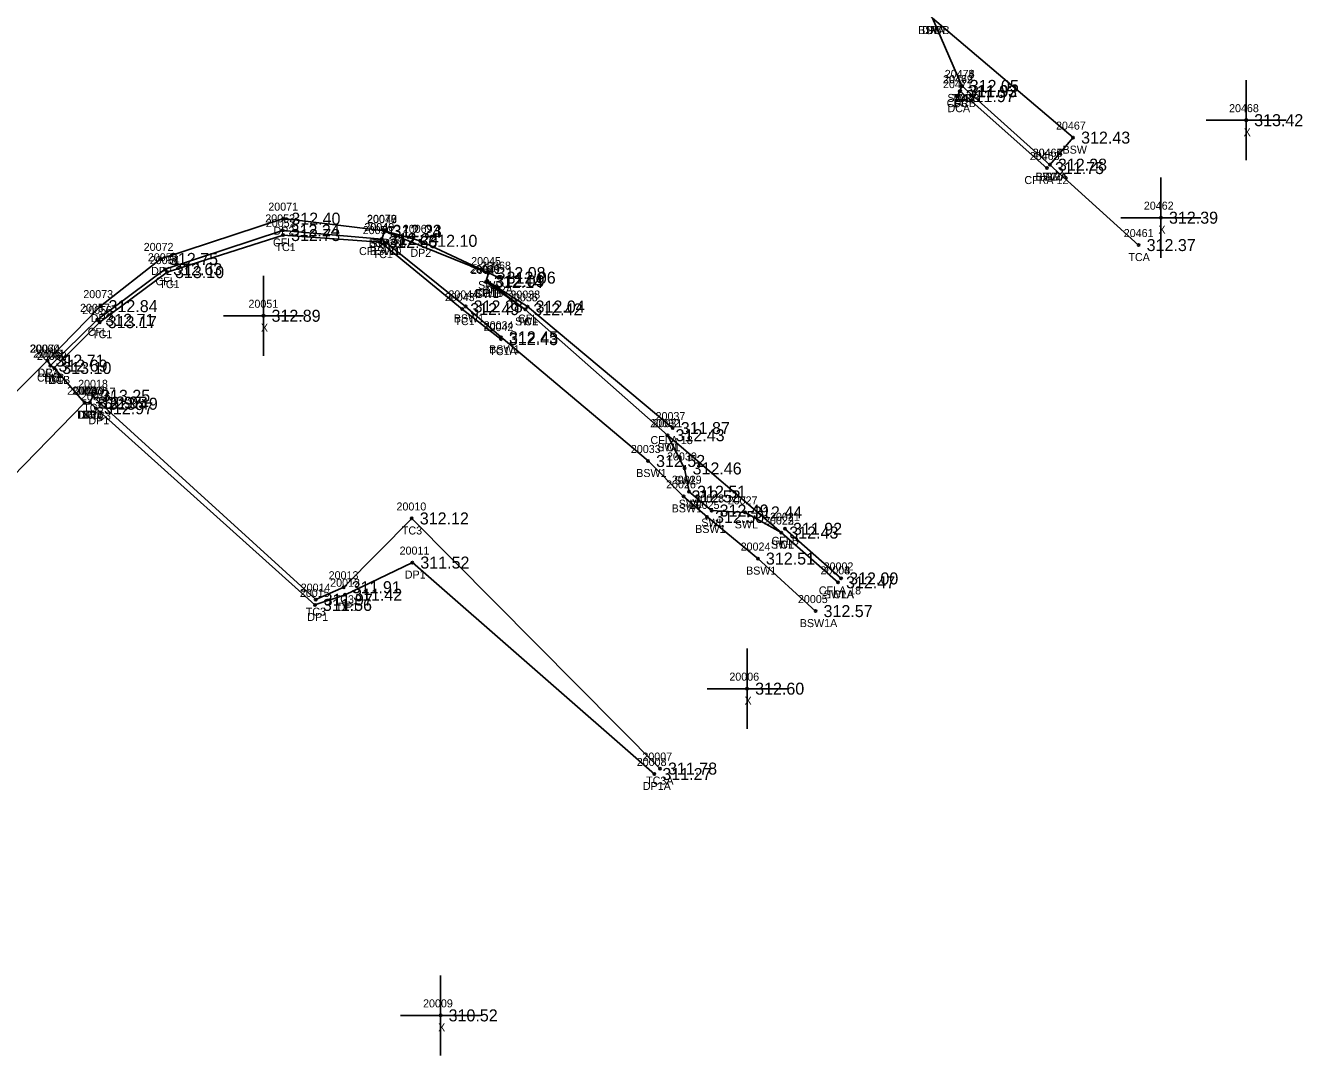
# Model space of a CAD drawing. Extents: x 1970242 to 1971082, y 803104 to 803947.
# Drawn here: x 1970893.2 to 1971052.8, y 803104.4 to 803233.1 of the extents above; entities that cross this region are included whole.
import ezdxf

# ---------------------------------------------------------------- set-up
doc = ezdxf.new("R2010")
doc.units = 0
for name, color, linetype in [('RD_DTM_BkLn2', 7, 'Continuous'), ('RD_EX_Conc', 7, 'Continuous'), ('RD_EX_Conc_txCode', 7, 'Continuous'), ('RD_EX_Driveway', 7, 'Continuous'), ('RD_EX_Driveway_txCode', 7, 'Continuous'), ('RD_EX_Misc', 7, 'Continuous'), ('RD_EX_Misc_txCode', 7, 'Continuous'), ('RD_EX_TX_Conc_ELEV', 7, 'Continuous'), ('RD_EX_TX_Driveway_ELEV', 7, 'Continuous'), ('RD_EX_TX_Misc_ELEV', 7, 'Continuous'), ('RD_SMD_Locator', 7, 'Continuous')]:
    doc.layers.add(name, color=color, linetype=linetype)

msp = doc.modelspace()

# ---------------------------------------------------------------- linework, layer by layer
at = {"layer": 'RD_DTM_BkLn2'}
for points in [[(1971032.36, 803205.64), (1971021.27, 803215.68), (1971010.25, 803225.52)], [(1970952.66, 803193.89), (1970947.82, 803197.64), (1970937.59, 803206.01), (1970925.44, 803206.89), (1970910.93, 803202.26), (1970902.52, 803196.01), (1970896.84, 803190.29)], [(1970994.79, 803163.51), (1970987.7, 803169.73), (1970973.48, 803181.89), (1970955.71, 803197.61), (1970950.97, 803201.14)], [(1970972.54, 803140.25), (1970941.52, 803171.49), (1970933.01, 803162.9), (1970929.51, 803161.35), (1970902.64, 803185.82), (1970901.69, 803186.81), (1970901.29, 803185.97)]]:
    msp.add_lwpolyline(points, dxfattribs=at)
at = {"layer": 'RD_EX_Conc'}
for p, q in [((1971021.27, 803215.68), (1971010.25, 803225.52)), ((1971020.9, 803215.26), (1971010.07, 803224.87)), ((1970995.18, 803164), (1970988.16, 803170.2))]:
    msp.add_line(p, q, dxfattribs=at)
for points in [[(1971009.74, 803224.24), (1971010.01, 803224.85), (1971010.25, 803225.52), (1971006.59, 803233.99), (1970934.65, 803298.46), (1970929.07, 803297.51), (1970928.19, 803297.32), (1970927.5, 803297.02)], [(1971021.27, 803215.68), (1971024.17, 803219.06), (1971006.59, 803233.99)], [(1970937.76, 803206.39), (1970925.37, 803207.47), (1970910.7, 803202.62), (1970902.22, 803196.3), (1970896.36, 803190.58)], [(1970991.98, 803159.92), (1970984.78, 803166.48), (1970978.42, 803171.68), (1970975.48, 803174.25), (1970971.05, 803178.67), (1970952.67, 803194.12), (1970948.25, 803197.98), (1970937.76, 803206.39), (1970938.1, 803207.37)], [(1970994.79, 803163.51), (1970987.7, 803169.73), (1970983.17, 803172.25), (1970978.99, 803172.48), (1970976.18, 803174.83), (1970975.61, 803177.74), (1970973.48, 803181.89), (1970955.71, 803197.61), (1970950.79, 803201.04), (1970951.1, 803202.14), (1970938.1, 803207.37)], [(1970974.14, 803182.78), (1970955.99, 803197.96), (1970950.97, 803201.14)], [(1970895.99, 803191.21), (1970896.36, 803190.58), (1970896.84, 803190.29), (1970900.63, 803185.94), (1970885.6, 803170.52), (1970879.45, 803174.56)]]:
    msp.add_lwpolyline(points, dxfattribs=at)
at = {"layer": 'RD_EX_Driveway'}
for points in [[(1970952.37, 803201.57), (1970942.58, 803206.17), (1970938.12, 803207.42), (1970925.47, 803208.94), (1970910.17, 803203.91), (1970902.62, 803198.01), (1970895.99, 803191.21), (1970879.38, 803174.75)], [(1970971.84, 803139.57), (1970941.59, 803165.98), (1970933.19, 803161.96), (1970929.41, 803160.69), (1970902.05, 803185.25), (1970901.29, 803185.97), (1970900.63, 803185.94), (1970885.6, 803170.52)]]:
    msp.add_lwpolyline(points, dxfattribs=at)
at = {"layer": 'RD_EX_Misc'}
for p, q in [((1971045.8, 803216.24), (1971045.8, 803226.24)), ((1971040.8, 803221.24), (1971050.8, 803221.24)), ((1971035.15, 803204.06), (1971035.15, 803214.06)), ((1971030.15, 803209.06), (1971040.15, 803209.06)), ((1970922.99, 803191.81), (1970922.99, 803201.81)), ((1970917.99, 803196.81), (1970927.99, 803196.81)), ((1970983.43, 803145.23), (1970983.43, 803155.23)), ((1970978.43, 803150.23), (1970988.43, 803150.23)), ((1970945.12, 803104.42), (1970945.12, 803114.42)), ((1970940.12, 803109.42), (1970950.12, 803109.42))]:
    msp.add_line(p, q, dxfattribs=at)
at = {"layer": 'RD_SMD_Locator'}
for centre in [(1971010.25, 803225.52), (1971010.25, 803225.52), (1971010.25, 803225.52), (1971009.74, 803224.24), (1971010.01, 803224.85), (1971010.07, 803224.87), (1971045.8, 803221.24), (1971024.17, 803219.06), (1971021.27, 803215.68), (1971021.27, 803215.68), (1971021.27, 803215.68), (1971020.9, 803215.26), (1970925.47, 803208.94), (1971035.15, 803209.06), (1970925.37, 803207.47), (1970925.44, 803206.89), (1970937.76, 803206.39), (1970937.76, 803206.39), (1970938.1, 803207.37), (1970938.1, 803207.37), (1970938.12, 803207.42), (1970942.58, 803206.17), (1970937.59, 803206.01), (1971032.36, 803205.64), (1970910.17, 803203.91), (1970910.7, 803202.62), (1970910.93, 803202.26), (1970951.1, 803202.14), (1970952.37, 803201.57), (1970950.79, 803201.04), (1970950.97, 803201.14), (1970950.97, 803201.14), (1970902.62, 803198.01), (1970922.99, 803196.81), (1970947.82, 803197.64), (1970948.25, 803197.98), (1970955.71, 803197.61), (1970955.71, 803197.61), (1970955.99, 803197.96), (1970902.22, 803196.3), (1970902.52, 803196.01), (1970952.66, 803193.89), (1970952.67, 803194.12), (1970895.99, 803191.21), (1970895.99, 803191.21), (1970896.36, 803190.58), (1970896.36, 803190.58), (1970896.84, 803190.29), (1970896.84, 803190.29), (1970900.63, 803185.94), (1970900.63, 803185.94), (1970901.29, 803185.97), (1970901.29, 803185.97), (1970901.69, 803186.81), (1970902.64, 803185.82), (1970902.05, 803185.25), (1970974.14, 803182.78), (1970973.48, 803181.89), (1970973.48, 803181.89), (1970971.05, 803178.67), (1970975.61, 803177.74), (1970975.48, 803174.25), (1970976.18, 803174.83), (1970941.52, 803171.49), (1970978.42, 803171.68), (1970978.99, 803172.48), (1970983.17, 803172.25), (1970987.7, 803169.73), (1970987.7, 803169.73), (1970988.16, 803170.2), (1970984.78, 803166.48), (1970941.59, 803165.98), (1970994.79, 803163.51), (1970994.79, 803163.51), (1970995.18, 803164), (1970933.01, 803162.9), (1970933.19, 803161.96), (1970929.41, 803160.69), (1970929.51, 803161.35), (1970991.98, 803159.92), (1970983.43, 803150.23), (1970971.84, 803139.57), (1970972.54, 803140.25), (1970945.12, 803109.42)]:
    msp.add_circle(centre, 0.15, dxfattribs=at)

# ---------------------------------------------------------------- texts
at = {"layer": 'RD_EX_Conc_txCode'}
for s, p in [('BSWB', (1971004.8, 803231.99)), ('DC', (1971005.81, 803231.99)), ('20473', (1971008.13, 803226.52)), ('20474', (1971008.13, 803226.52)), ('20475', (1971008.13, 803226.52)), ('20472', (1971007.9, 803225.85)), ('20471', (1971007.91, 803225.24)), ('20469', (1971007.93, 803225.87)), ('CFRB', (1971008.37, 803222.87)), ('SWRB', (1971008.46, 803223.52)), ('TCB', (1971008.98, 803223.52)), ('DC', (1971009.23, 803222.85)), ('DC', (1971009.47, 803223.52)), ('DCA', (1971008.47, 803222.24)), ('20467', (1971022.03, 803220.06)), ('20466', (1971019.11, 803216.68)), ('20464', (1971019.13, 803216.68)), ('20465', (1971019.13, 803216.68)), ('BSW', (1971022.85, 803217.06)), ('20463', (1971018.76, 803216.26)), ('CFRA 12', (1971018.08, 803213.26)), ('SWRA', (1971019.47, 803213.68)), ('BSWA', (1971019.47, 803213.68)), ('TC', (1971020.48, 803213.68)), ('20053', (1970923.21, 803208.47)), ('20052', (1970923.28, 803207.89)), ('20050', (1970935.39, 803207.01)), ('20046', (1970935.58, 803207.39)), ('20049', (1970935.61, 803207.39)), ('20047', (1970935.94, 803208.37)), ('20048', (1970935.94, 803208.37)), ('CFL', (1970924.17, 803205.47)), ('BSW1B', (1970936.14, 803205.37)), ('SWLB', (1970936.33, 803205.37)), ('20461', (1971030.5, 803206.64)), ('TC1', (1970924.48, 803204.89)), ('CFLA 10', (1970934.93, 803204.39)), ('BSW1', (1970936.28, 803204.39)), ('TC1', (1970936.62, 803204.01)), ('TCA', (1971031.08, 803203.64)), ('20055', (1970908.54, 803203.62)), ('20054', (1970908.77, 803203.26)), ('20040', (1970948.77, 803202.14)), ('20039', (1970948.81, 803202.14)), ('20041', (1970948.91, 803202.04)), ('20045', (1970948.94, 803203.14)), ('CFL', (1970909.49, 803200.62)), ('TC1', (1970909.97, 803200.26)), ('20044', (1970946.1, 803198.98)), ('CFLB', (1970949.29, 803199.14)), ('SWL', (1970949.5, 803199.04)), ('TC1B', (1970949.54, 803199.14)), ('SWL', (1970949.81, 803200.14)), ('20038', (1970953.84, 803198.96)), ('20057', (1970900.06, 803197.3)), ('20043', (1970945.66, 803198.64)), ('20036', (1970953.53, 803198.61)), ('20035', (1970953.55, 803198.61)), ('20056', (1970900.34, 803197.01)), ('BSW1', (1970946.77, 803195.98)), ('CFL', (1970954.79, 803195.96)), ('CFL', (1970901.01, 803194.3)), ('TC1', (1970946.85, 803195.64)), ('20042', (1970950.5, 803194.89)), ('20034', (1970950.51, 803195.12)), ('SWL', (1970954.42, 803195.61)), ('TC1', (1970954.75, 803195.61)), ('TC1', (1970901.56, 803194.01)), ('20060', (1970893.77, 803192.21)), ('20058', (1970894.2, 803191.58)), ('20061', (1970894.46, 803191.58)), ('20062', (1970894.66, 803191.29)), ('20059', (1970894.69, 803191.29)), ('TC1A', (1970951.21, 803191.89)), ('BSW1', (1970951.19, 803192.12)), ('CFLB', (1970894.68, 803188.58)), ('DCA', (1970894.73, 803189.21)), ('TC1B', (1970895.41, 803188.29)), ('DC', (1970895.58, 803188.58)), ('DC', (1970896.06, 803188.29)), ('20018', (1970899.82, 803187.81)), ('20063', (1970898.45, 803186.94)), ('20019', (1970899.41, 803186.97)), ('20017', (1970900.77, 803186.82)), ('TC3', (1970900.45, 803184.81)), ('TC3B', (1970899.57, 803183.97)), ('DC', (1970899.85, 803183.94)), ('TC3', (1970901.4, 803183.82)), ('20032', (1970971.32, 803182.89)), ('20031', (1970971.6, 803182.89)), ('20037', (1970971.99, 803183.78)), ('CFLA 18', (1970971.35, 803180.78)), ('SWL', (1970972.19, 803179.89)), ('TC1', (1970972.52, 803179.89)), ('20033', (1970968.9, 803179.67)), ('20030', (1970973.42, 803178.74)), ('BSW1', (1970969.57, 803176.67)), ('20026', (1970973.3, 803175.25)), ('20029', (1970974.02, 803175.83)), ('SWL', (1970974.32, 803175.74)), ('20028', (1970976.83, 803173.48)), ('20010', (1970939.61, 803172.49)), ('BSW1', (1970974, 803172.25)), ('SWL', (1970974.89, 803172.83)), ('20025', (1970976.26, 803172.68)), ('20027', (1970981.01, 803173.25)), ('SWL', (1970977.7, 803170.48)), ('SWL', (1970981.88, 803170.25)), ('20022', (1970985.54, 803170.73)), ('20023', (1970985.54, 803170.73)), ('20021', (1970986.29, 803171.2)), ('TC3', (1970940.28, 803169.49)), ('BSW1', (1970976.94, 803169.68)), ('20024', (1970982.62, 803167.48)), ('SWL', (1970986.4, 803167.73)), ('CFLB', (1970986.48, 803168.2)), ('TC1', (1970986.74, 803167.73)), ('20013', (1970931.13, 803163.9)), ('BSW1', (1970983.3, 803164.48)), ('20003', (1970992.59, 803164.51)), ('20004', (1970992.59, 803164.51)), ('20002', (1970992.99, 803165)), ('20014', (1970927.64, 803162.35)), ('TC3', (1970931.76, 803160.9)), ('20005', (1970989.78, 803160.92)), ('CFLA 18', (1970992.39, 803162)), ('SWLA', (1970993.01, 803161.51)), ('TC1A', (1970993.34, 803161.51)), ('TC3', (1970928.27, 803159.35)), ('BSW1A', (1970990.01, 803157.92)), ('20007', (1970970.34, 803141.25)), ('TC3A', (1970970.81, 803138.25))]:
    msp.add_text(s, height=1, dxfattribs=at).set_placement(p)
at = {"layer": 'RD_EX_Driveway_txCode'}
for s, p in [('DPA', (1971005.32, 803231.99)), ('20071', (1970923.59, 803209.94)), ('20070', (1970935.92, 803208.42)), ('DP2', (1970924.24, 803206.94)), ('20069', (1970940.4, 803207.17)), ('DP2', (1970936.89, 803205.42)), ('20072', (1970908.02, 803204.91)), ('DP2', (1970941.35, 803204.17)), ('20068', (1970950.19, 803202.57)), ('DP2', (1970908.94, 803201.91)), ('20073', (1970900.47, 803199.01)), ('DP2A', (1970950.65, 803199.57)), ('DP2', (1970901.4, 803196.01)), ('20074', (1970893.84, 803192.21)), ('DP2', (1970894.76, 803189.21)), ('20064', (1970898.45, 803186.94)), ('20020', (1970899.09, 803186.97)), ('20016', (1970900.16, 803186.25)), ('DP1', (1970899.68, 803183.94)), ('DP1', (1970900.34, 803183.97)), ('DP1', (1970901.11, 803183.25)), ('20011', (1970940, 803166.98)), ('DP1', (1970940.65, 803163.98)), ('20012', (1970931.32, 803162.96)), ('20015', (1970927.53, 803161.69)), ('DP1', (1970932.25, 803159.96)), ('DP1', (1970928.46, 803158.69)), ('20008', (1970969.64, 803140.57)), ('DP1A', (1970970.4, 803137.57))]:
    msp.add_text(s, height=1, dxfattribs=at).set_placement(p)
at = {"layer": 'RD_EX_Misc_txCode'}
for s, p in [('20468', (1971043.66, 803222.24)), ('X', (1971045.48, 803219.24)), ('20462', (1971033.01, 803210.06)), ('X', (1971034.83, 803207.06)), ('20051', (1970921.11, 803197.81)), ('X', (1970922.67, 803194.81)), ('20006', (1970981.21, 803151.23)), ('X', (1970983.11, 803148.23)), ('20009', (1970942.93, 803110.42)), ('X', (1970944.81, 803107.42))]:
    msp.add_text(s, height=1, dxfattribs=at).set_placement(p)
at = {"layer": 'RD_EX_TX_Conc_ELEV'}
for s, p in [('311.93', (1971011.01, 803224.1)), ('311.92', (1971011.07, 803224.12)), ('312.05', (1971011.25, 803224.77)), ('312.05', (1971011.25, 803224.77)), ('312.05', (1971011.25, 803224.77)), ('311.97', (1971010.74, 803223.49)), ('312.43', (1971025.17, 803218.31)), ('311.75', (1971021.9, 803214.51)), ('312.28', (1971022.27, 803214.93)), ('312.28', (1971022.27, 803214.93)), ('312.28', (1971022.27, 803214.93)), ('312.24', (1970926.37, 803206.72)), ('312.24', (1970939.1, 803206.62)), ('312.24', (1970939.1, 803206.62)), ('312.73', (1970926.44, 803206.14)), ('312.60', (1970938.59, 803205.26)), ('312.24', (1970938.76, 803205.64)), ('312.24', (1970938.76, 803205.64)), ('312.37', (1971033.36, 803204.89)), ('312.63', (1970911.7, 803201.87)), ('313.10', (1970911.93, 803201.51)), ('312.14', (1970951.79, 803200.29)), ('312.09', (1970951.97, 803200.39)), ('312.09', (1970951.97, 803200.39)), ('312.08', (1970952.1, 803201.39)), ('312.49', (1970948.82, 803196.89)), ('312.28', (1970949.25, 803197.23)), ('312.42', (1970956.71, 803196.86)), ('312.42', (1970956.71, 803196.86)), ('312.04', (1970956.99, 803197.21)), ('312.71', (1970903.22, 803195.55)), ('313.17', (1970903.52, 803195.26)), ('312.43', (1970953.66, 803193.14)), ('312.45', (1970953.67, 803193.37)), ('312.71', (1970896.99, 803190.46)), ('312.69', (1970897.36, 803189.83)), ('312.69', (1970897.36, 803189.83)), ('313.10', (1970897.84, 803189.54)), ('313.10', (1970897.84, 803189.54)), ('313.25', (1970902.69, 803186.06)), ('312.97', (1970901.63, 803185.19)), ('312.95', (1970902.29, 803185.22)), ('313.49', (1970903.64, 803185.07)), ('312.43', (1970974.48, 803181.14)), ('312.43', (1970974.48, 803181.14)), ('311.87', (1970975.14, 803182.03)), ('312.52', (1970972.05, 803177.92)), ('312.46', (1970976.61, 803176.99)), ('312.52', (1970976.48, 803173.5)), ('312.51', (1970977.18, 803174.08)), ('312.49', (1970979.99, 803171.73)), ('312.44', (1970984.17, 803171.5)), ('312.12', (1970942.52, 803170.74)), ('312.50', (1970979.42, 803170.93)), ('312.43', (1970988.7, 803168.98)), ('312.43', (1970988.7, 803168.98)), ('311.92', (1970989.16, 803169.45)), ('312.51', (1970985.78, 803165.73)), ('312.00', (1970996.18, 803163.25)), ('311.91', (1970934.01, 803162.15)), ('312.47', (1970995.79, 803162.76)), ('312.47', (1970995.79, 803162.76)), ('311.97', (1970930.51, 803160.6)), ('312.57', (1970992.98, 803159.17)), ('311.78', (1970973.54, 803139.5))]:
    msp.add_text(s, height=1.5, dxfattribs=at).set_placement(p)
at = {"layer": 'RD_EX_TX_Driveway_ELEV'}
for s, p in [('312.40', (1970926.47, 803208.19)), ('312.23', (1970939.12, 803206.67)), ('312.10', (1970943.58, 803205.42)), ('312.75', (1970911.17, 803203.16)), ('312.06', (1970953.37, 803200.82)), ('312.84', (1970903.62, 803197.26)), ('312.71', (1970896.99, 803190.46)), ('312.97', (1970901.63, 803185.19)), ('312.95', (1970902.29, 803185.22)), ('312.97', (1970903.05, 803184.5)), ('311.52', (1970942.59, 803165.23)), ('311.42', (1970934.19, 803161.21)), ('311.56', (1970930.41, 803159.94)), ('311.27', (1970972.84, 803138.82))]:
    msp.add_text(s, height=1.5, dxfattribs=at).set_placement(p)
at = {"layer": 'RD_EX_TX_Misc_ELEV'}
for s, p in [('313.42', (1971046.8, 803220.49)), ('312.39', (1971036.15, 803208.31)), ('312.89', (1970923.99, 803196.06)), ('312.60', (1970984.43, 803149.48)), ('310.52', (1970946.12, 803108.67))]:
    msp.add_text(s, height=1.5, dxfattribs=at).set_placement(p)

doc.saveas('drawing.dxf')
